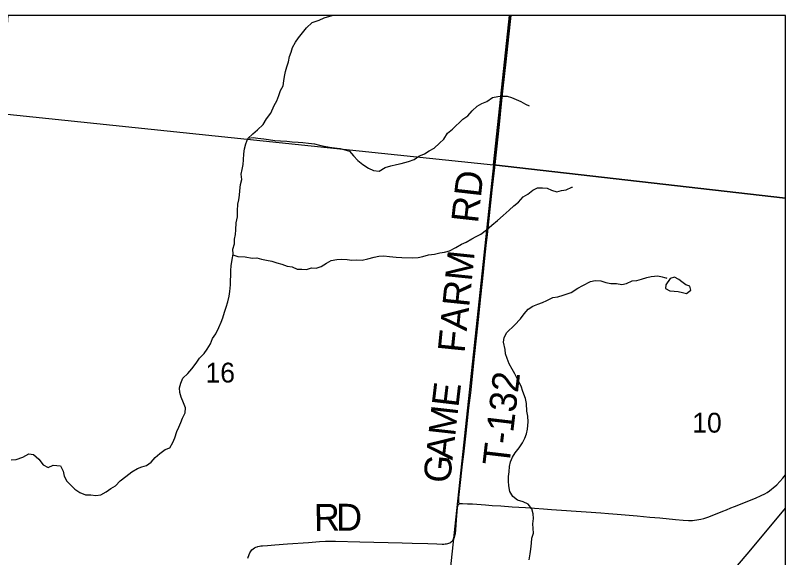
# Model space of a CAD drawing. Extents: x 0 to 1067, y 0 to 440.
# Drawn here: x 803.215 to 804.84, y 356.458 to 357.602 of the extents above; entities that cross this region are included whole.
import ezdxf

# ---------------------------------------------------------------- set-up
doc = ezdxf.new("R2010")
doc.units = 0
for name, color, linetype in [('GM_X_County_Road', 7, 'Continuous'), ('GM_X_County_Road_Text', 7, 'Continuous'), ('GM_X_Minor_Lake', 7, 'Continuous'), ('GM_X_Minor_River', 7, 'Continuous'), ('GM_X_Rail_Line', 7, 'Continuous'), ('GM_X_Section', 7, 'Continuous'), ('GM_X_Section_Text', 7, 'Continuous'), ('GM_X_Township_Road', 7, 'Continuous'), ('GM_X_Township_Road_Text', 7, 'Continuous'), ('GM_X_US_Shield', 7, 'Continuous')]:
    doc.layers.add(name, color=color, linetype=linetype)

msp = doc.modelspace()

# ---------------------------------------------------------------- linework, layer by layer
at = {"layer": 'GM_X_County_Road'}
for points in [[(804.1519, 356.5715), (804.1531, 356.5719), (804.1543, 356.5721), (804.1555, 356.5722), (804.1566, 356.5722), (804.1582, 356.5721), (804.1687, 356.5717), (804.1798, 356.5712), (804.1885, 356.5705), (804.2071, 356.569), (804.2207, 356.568), (804.2393, 356.5668), (804.2634, 356.5652), (804.2913, 356.5633), (804.3291, 356.5606), (804.3465, 356.5594), (804.419, 356.5544), (804.4506, 356.5522), (804.4667, 356.5512), (804.4847, 356.5497), (804.5267, 356.546), (804.5533, 356.5434), (804.575, 356.5415), (804.6078, 356.5384), (804.6239, 356.537), (804.6351, 356.5364), (804.6439, 356.5365), (804.6479, 356.5368), (804.6526, 356.5373), (804.6567, 356.538), (804.6612, 356.5389), (804.6679, 356.5407), (804.6762, 356.5434), (804.6885, 356.548), (804.7075, 356.5556), (804.7155, 356.5589), (804.7247, 356.5628), (804.7322, 356.5658), (804.7766, 356.5836), (804.7887, 356.5887), (804.7965, 356.5926), (804.8013, 356.5956), (804.806, 356.5988), (804.8101, 356.602), (804.8138, 356.605), (804.8213, 356.6117), (804.8279, 356.6183), (804.8342, 356.6252), (804.8401, 356.6324)], [(803.7053, 356.4566), (803.708, 356.4641), (803.7097, 356.468), (803.7108, 356.4702), (803.7121, 356.4721), (803.7141, 356.4745), (803.7165, 356.4766), (803.7192, 356.4785), (803.7224, 356.48), (803.7249, 356.4809), (803.7268, 356.4815), (803.7299, 356.4822), (803.733, 356.4825), (803.7365, 356.4828), (803.7472, 356.4837), (803.7621, 356.4847), (803.7894, 356.4867), (803.8333, 356.49), (803.8563, 356.4916), (803.8693, 356.4923), (803.8767, 356.4925), (803.8903, 356.4925), (803.9419, 356.4915), (804.0307, 356.4894), (804.0524, 356.4886), (804.0853, 356.4875), (804.104, 356.4867), (804.1155, 356.4862), (804.1191, 356.4864), (804.1217, 356.4866), (804.1248, 356.4871), (804.1272, 356.4875), (804.1296, 356.4882), (804.1315, 356.4891), (804.1337, 356.4905), (804.1353, 356.4918), (804.137, 356.4935), (804.1389, 356.4958), (804.1404, 356.4983), (804.1413, 356.5003), (804.1423, 356.5032), (804.143, 356.5064), (804.1434, 356.5086), (804.1438, 356.5107), (804.144, 356.5135), (804.1443, 356.5164), (804.1459, 356.5376), (804.1479, 356.5626), (804.1481, 356.5644), (804.1485, 356.5663), (804.1488, 356.5675), (804.1491, 356.5685), (804.1494, 356.5692), (804.1499, 356.5699), (804.1504, 356.5705), (804.1509, 356.571), (804.1519, 356.5715)]]:
    msp.add_lwpolyline(points, dxfattribs=at)
at = {"layer": 'GM_X_Minor_Lake'}
for points in [[(804.6373, 357.0203), (804.6399, 357.0224), (804.6381, 357.0304), (804.6294, 357.0335), (804.6212, 357.0397), (804.6148, 357.0451), (804.6054, 357.0494), (804.5966, 357.0469), (804.5873, 357.0334)], [(804.5873, 357.0334), (804.5864, 357.0258), (804.5958, 357.0208), (804.6049, 357.0203), (804.6133, 357.0194), (804.6227, 357.0174), (804.6311, 357.0154), (804.6373, 357.0203)]]:
    msp.add_lwpolyline(points, dxfattribs=at)
at = {"layer": 'GM_X_Minor_River'}
for points in [[(803.5962, 356.868), (803.6035, 356.8786), (803.6131, 356.8887), (803.6193, 356.8981), (803.6263, 356.9091), (803.6309, 356.9204), (803.6375, 356.9299), (803.6441, 356.9435), (803.6491, 356.9544), (803.6527, 356.9639), (803.6562, 356.9756), (803.6597, 356.9866), (803.6633, 356.9979), (803.666, 357.0097), (803.6673, 357.0195), (803.6685, 357.0332), (803.6686, 357.0427), (803.6695, 357.0529), (803.6696, 357.0635), (803.67, 357.0737), (803.6724, 357.087), (803.6741, 357.0984), (803.6738, 357.1086), (803.6773, 357.12), (803.677, 357.1298), (803.6794, 357.1397), (803.6803, 357.1495), (803.6808, 357.1643), (803.6836, 357.1768), (803.6833, 357.1897), (803.6842, 357.2037), (803.6862, 357.2132), (803.6878, 357.2226), (803.6886, 357.2321), (803.6899, 357.245), (803.6927, 357.2559), (803.6916, 357.2669), (803.6933, 357.2772), (803.6956, 357.2874), (803.6961, 357.2976), (803.6966, 357.3097), (803.6986, 357.3207), (803.7014, 357.3313), (803.7053, 357.3426), (803.7157, 357.3524), (803.7256, 357.3606), (803.7379, 357.3719), (803.7445, 357.3839), (803.7541, 357.3956), (803.7608, 357.4122), (803.7666, 357.4216), (803.7709, 357.4329), (803.7744, 357.4435), (803.7802, 357.4537), (803.7814, 357.4639), (803.783, 357.4734), (803.785, 357.4839), (803.7878, 357.4938), (803.7909, 357.504), (803.7933, 357.5153), (803.7965, 357.5248), (803.7996, 357.5346), (803.8062, 357.5455), (803.8124, 357.5549), (803.8205, 357.5654), (803.8293, 357.5756), (803.8412, 357.5868), (803.8561, 357.592), (803.8661, 357.5968), (803.8834, 357.6021)], [(803.7058, 357.3431), (803.7163, 357.3444), (803.7262, 357.3432), (803.7392, 357.3415), (803.7487, 357.3399), (803.7624, 357.3383), (803.7745, 357.3374), (803.7875, 357.3365), (803.7989, 357.3353), (803.8114, 357.3344), (803.8217, 357.3339), (803.8331, 357.3323), (803.8461, 357.3314), (803.8563, 357.3283), (803.8662, 357.3259), (803.8776, 357.3243), (803.8882, 357.3226), (803.9004, 357.3214), (803.9103, 357.3183), (803.9198, 357.3155), (803.9284, 357.3056), (803.9375, 357.296), (803.9477, 357.2872), (803.9602, 357.2795), (803.9704, 357.2748), (803.9822, 357.2736), (803.9952, 357.281), (804.0071, 357.2843), (804.0193, 357.2872), (804.0292, 357.2894), (804.0441, 357.2938), (804.0563, 357.2983), (804.0659, 357.305), (804.0781, 357.3098), (804.0881, 357.3165), (804.0984, 357.3221), (804.1095, 357.3322), (804.1191, 357.3409), (804.1269, 357.3533), (804.1372, 357.3619), (804.1587, 357.3829), (804.1695, 357.3901), (804.1787, 357.4006), (804.1891, 357.4103), (804.199, 357.4159), (804.2097, 357.4207), (804.2216, 357.4286), (804.2331, 357.4311), (804.2426, 357.4314), (804.2525, 357.4317), (804.262, 357.429), (804.2718, 357.4243), (804.2813, 357.4204), (804.2915, 357.415), (804.2991, 357.4112)], [(803.6738, 357.0968), (803.6843, 357.0933), (803.6999, 357.0924), (803.7147, 357.09), (803.7246, 357.0903), (803.7345, 357.0875), (803.7448, 357.0859), (803.7558, 357.0835), (803.7664, 357.08), (803.7774, 357.0769), (803.7881, 357.073), (803.7991, 357.0717), (803.8097, 357.0667), (803.8192, 357.0666), (803.8295, 357.0657), (803.8398, 357.0694), (803.8493, 357.0686), (803.8604, 357.0719), (803.8711, 357.079), (803.8815, 357.0846), (803.8929, 357.0871), (803.9039, 357.0874), (803.915, 357.0873), (803.9245, 357.0856), (803.9352, 357.0863), (803.9469, 357.0854), (803.9588, 357.0883), (803.9721, 357.0916), (803.9817, 357.0938), (803.992, 357.0945), (804.0045, 357.0936), (804.0186, 357.0919), (804.0304, 357.091), (804.0528, 357.0908), (804.065, 357.0911), (804.0746, 357.0933), (804.0868, 357.0966), (804.0994, 357.0983), (804.1104, 357.1009), (804.1207, 357.1027), (804.1307, 357.1056), (804.1444, 357.1123), (804.1563, 357.119), (804.1659, 357.1238), (804.1777, 357.1306), (804.1873, 357.1354), (804.1968, 357.1406), (804.2087, 357.1496), (804.2199, 357.1594), (804.2321, 357.1695), (804.2444, 357.18), (804.2567, 357.1909), (804.2667, 357.1999), (804.2763, 357.2081), (804.2867, 357.219), (804.2962, 357.2246), (804.307, 357.2336), (804.3169, 357.2384), (804.3272, 357.238), (804.3367, 357.2375), (804.3462, 357.2336), (804.3576, 357.2297), (804.3671, 357.2326), (804.3774, 357.2337), (804.3889, 357.2396), (804.3908, 357.2396)], [(804.2882, 356.9723), (804.297, 356.9825), (804.307, 356.9888), (804.3173, 356.9929), (804.3269, 356.9962), (804.3364, 357.0007), (804.3487, 357.0066), (804.3593, 357.0084), (804.3708, 357.0117), (804.388, 357.0173), (804.4014, 357.0266), (804.4121, 357.0322), (804.4286, 357.0404), (804.4381, 357.043), (804.4506, 357.0421), (804.4605, 357.0382), (804.4712, 357.0362), (804.483, 357.0361), (804.4947, 357.0344), (804.5047, 357.0362), (804.5161, 357.0418), (804.526, 357.0425), (804.5363, 357.0454), (804.547, 357.0491), (804.5566, 357.0513), (804.5703, 357.0523), (804.5798, 357.0503), (804.5893, 357.0475), (804.5889, 357.0475)], [(804.2991, 356.4535), (804.3011, 356.4657), (804.3027, 356.4759), (804.3036, 356.4881), (804.3048, 356.4991), (804.3079, 356.5093), (804.3077, 356.5192), (804.3066, 356.5291), (804.3082, 356.5405), (804.3076, 356.55), (804.305, 356.5611), (804.2967, 356.5707), (804.2865, 356.5753), (804.2747, 356.5789), (804.2649, 356.587), (804.2585, 356.5977), (804.2563, 356.6091), (804.2553, 356.6194), (804.2557, 356.6293), (804.257, 356.6391), (804.2574, 356.6498), (804.2598, 356.66), (804.2641, 356.6695), (804.2695, 356.6793), (804.2776, 356.6895), (804.2849, 356.7004), (804.29, 356.7099), (804.2931, 356.7193), (804.2955, 356.7288), (804.2971, 356.7444), (804.2965, 356.7561), (804.2943, 356.7668), (804.2937, 356.7831), (804.2915, 356.7938), (804.2855, 356.8083), (804.2822, 356.8197), (804.2762, 356.83), (804.2691, 356.8457), (804.2631, 356.8552), (804.2571, 356.8667), (804.2523, 356.8778), (804.2493, 356.8877), (804.2487, 356.8972), (804.245, 356.9128), (804.2462, 356.9226), (804.252, 356.9332), (804.2678, 356.9482), (804.2809, 356.9618), (804.2882, 356.9723)], [(803.2063, 356.664), (803.2163, 356.665), (803.2308, 356.6698), (803.2434, 356.6769), (803.2529, 356.6753), (803.2642, 356.6657), (803.2736, 356.6535), (803.2839, 356.648), (803.2946, 356.6533), (803.3098, 356.6516), (803.3158, 356.6401), (803.3176, 356.6298), (803.3232, 356.6195), (803.3406, 356.6022), (803.3508, 356.5953), (803.3625, 356.5906), (803.3743, 356.5901), (803.3846, 356.5889), (803.3953, 356.5903), (803.4064, 356.5967), (803.416, 356.6038), (803.4263, 356.6094), (803.4363, 356.6196), (803.4478, 356.6289), (803.4604, 356.6387), (803.4723, 356.6458), (803.4819, 356.6495), (803.4918, 356.6525), (803.5014, 356.6592), (803.5095, 356.669), (803.5198, 356.6777), (803.5309, 356.6863), (803.5409, 356.6896), (803.5471, 356.7006), (803.551, 356.7108), (803.5553, 356.7237), (803.5599, 356.7331), (803.5638, 356.743), (803.5677, 356.7524), (803.5731, 356.7634), (803.5736, 356.7736), (803.5695, 356.7847), (803.5647, 356.7965), (803.5617, 356.8061), (803.5611, 356.8159), (803.5638, 356.8258), (803.5681, 356.8364), (803.5785, 356.8461), (803.5873, 356.8563), (803.5962, 356.868)]]:
    msp.add_lwpolyline(points, dxfattribs=at)
at = {"layer": 'GM_X_Rail_Line'}
msp.add_lwpolyline([(802.6661, 353.2687), (802.697, 353.3096), (802.7308, 353.3638), (802.8122, 353.4875), (802.8565, 353.5668), (802.8978, 353.6472), (802.9601, 353.7689), (803.2011, 354.2396), (803.4754, 354.7705), (803.5751, 354.9733), (803.6255, 355.0706), (803.6726, 355.1455), (803.7251, 355.2226), (803.7723, 355.2875), (803.8221, 355.3565), (804.0447, 355.6231), (804.2946, 355.9212), (804.7631, 356.4702), (804.8401, 356.5624)], dxfattribs=at)
at = {"layer": 'GM_X_Section'}
msp.add_lwpolyline([(804.224, 357.2865), (804.1217, 356.3334), (803.0664, 356.4332), (803.1843, 357.3948)], close=True, dxfattribs=at)
at = {"layer": 'GM_X_Township_Road'}
for points in [[(804.8401, 353.205), (804.8401, 357.6021), (800.0635, 357.6021)], [(804.1519, 356.5715), (804.1514, 356.5725), (804.1509, 356.5737), (804.1505, 356.5751), (804.1504, 356.5761), (804.1503, 356.5773), (804.1503, 356.5807), (804.1507, 356.585), (804.1534, 356.6101), (804.1586, 356.6552), (804.1611, 356.6762), (804.166, 356.7206), (804.172, 356.7737), (804.1757, 356.8058), (804.1787, 356.8329), (804.1832, 356.8756), (804.1886, 356.9275), (804.192, 356.9605), (804.197, 357.008), (804.2026, 357.0603), (804.2048, 357.0825), (804.2084, 357.1165), (804.2111, 357.14), (804.2213, 357.2332), (804.2264, 357.2808), (804.2307, 357.3197), (804.2361, 357.3722), (804.2406, 357.4155), (804.2436, 357.442), (804.2503, 357.5038), (804.2558, 357.5569), (804.2608, 357.6021)]]:
    msp.add_lwpolyline(points, dxfattribs=at)
at = {"layer": 'GM_X_US_Shield'}
for points in [[(804.2578, 357.6021), (803.1989, 357.6021), (803.1843, 357.3948), (804.224, 357.2865)], [(804.8401, 357.2164), (804.8401, 357.6021), (804.2578, 357.6021), (804.224, 357.2865)], [(804.8401, 356.2621), (804.8401, 357.2164), (804.224, 357.2865), (804.1217, 356.3334)]]:
    msp.add_lwpolyline(points, close=True, dxfattribs=at)

# ---------------------------------------------------------------- texts
at = {"layer": 'GM_X_County_Road_Text'}
for s, rotation, p in [('R', 1.0031, (803.8453, 356.5138)), ('D', 0.0474, (803.8917, 356.5146))]:
    msp.add_text(s, height=0.0568, rotation=rotation, dxfattribs=at).set_placement(p)
at = {"layer": 'GM_X_Section_Text'}
for s, p in [('16', (803.616, 356.8274)), ('10', (804.6431, 356.7216))]:
    msp.add_text(s, height=0.04186, rotation=0, dxfattribs=at).set_placement(p)
at = {"layer": 'GM_X_Township_Road_Text'}
for s, height, rotation, p in [('RD', 0.05682, 83.6054, (804.1909, 357.1623)), ('FARM', 0.05682, 84.1976, (804.1625, 356.8887)), ('T-132', 0.05682, 83.2931, (804.2569, 356.6494)), ('E', 0.0568, 83.2476, (804.1496, 356.7737)), ('M', 0.0568, 83.6546, (804.1428, 356.7125)), ('A', 0.0568, 83.6594, (804.1372, 356.6628)), ('G', 0.0568, 83.6594, (804.1317, 356.6132))]:
    msp.add_text(s, height=height, rotation=rotation, dxfattribs=at).set_placement(p)

doc.saveas('drawing.dxf')
